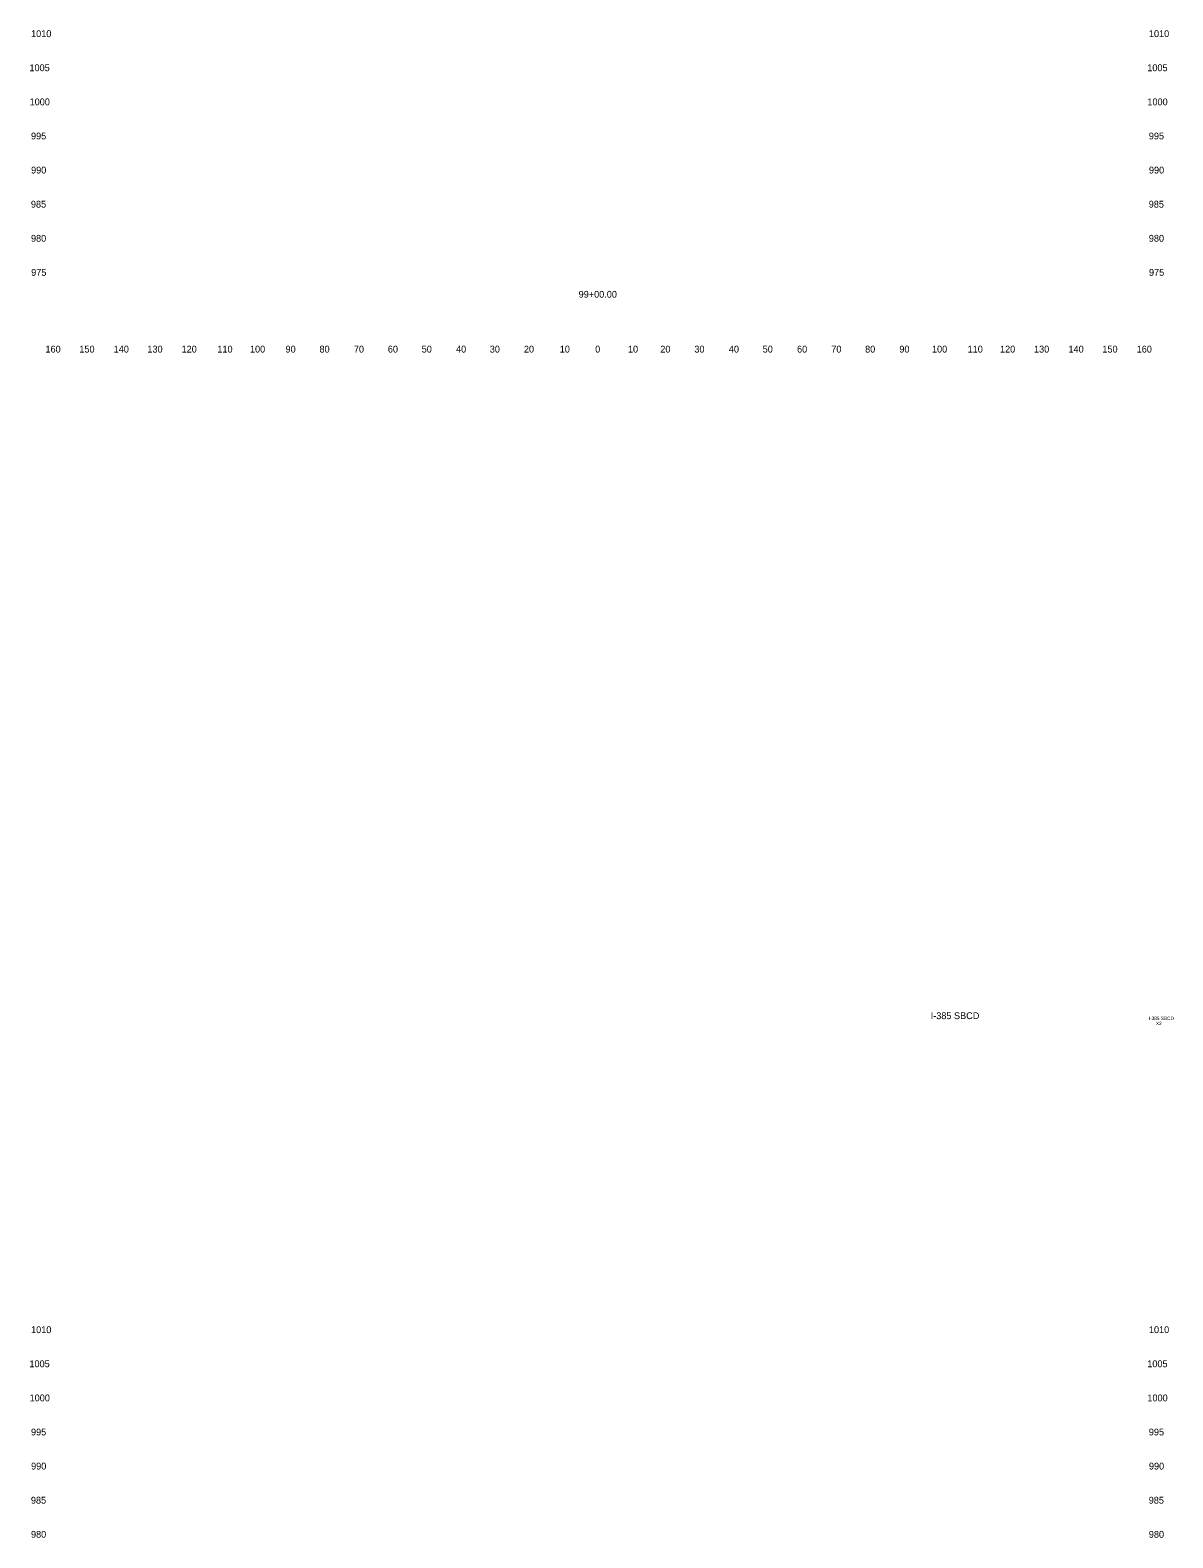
# Model space of a CAD drawing. Extents: x 4994 to 6876, y 4997 to 8804.
# Drawn here: x 4993.6 to 5328.7, y 5450 to 5892 of the extents above; entities that cross this region are included whole.
import ezdxf

# ---------------------------------------------------------------- set-up
doc = ezdxf.new("R2010")
doc.units = 0
for name, color, linetype in [('RD_SHT_ID', 7, 'Continuous'), ('RD_XS_TX_Offset', 7, 'Continuous'), ('RD_XS_TX_Station', 7, 'Continuous')]:
    doc.layers.add(name, color=color, linetype=linetype)

msp = doc.modelspace()

# ---------------------------------------------------------------- texts
at = {"layer": 'RD_SHT_ID'}
for s, height, p in [('I-385 SBCD', 2, (5257.69, 5602.06)), ('I-385 SBCD', 1, (5321.63, 5601.8)), ('X2', 1, (5323.74, 5600.3))]:
    msp.add_text(s, height=height, dxfattribs=at).set_placement(p)
at = {"layer": 'RD_XS_TX_Offset'}
for s, p in [('1010', (4993.88, 5890)), ('1010', (5321.68, 5890)), ('1005', (4993.4, 5880)), ('1005', (5321.2, 5880)), ('1000', (4993.44, 5870)), ('1000', (5321.24, 5870)), ('995', (4993.86, 5860)), ('995', (5321.66, 5860)), ('990', (4993.89, 5850)), ('990', (5321.69, 5850)), ('985', (4993.83, 5840)), ('985', (5321.63, 5840)), ('980', (4993.86, 5830)), ('980', (5321.66, 5830)), ('975', (4993.91, 5820)), ('975', (5321.71, 5820)), ('160', (4998.1, 5797.5)), ('150', (5008.04, 5797.5)), ('140', (5018.1, 5797.5)), ('130', (5027.99, 5797.5)), ('120', (5038.01, 5797.5)), ('110', (5048.51, 5797.5)), ('100', (5058.07, 5797.5)), ('90', (5068.5, 5797.5)), ('80', (5078.46, 5797.5)), ('70', (5088.54, 5797.5)), ('60', (5098.5, 5797.5)), ('50', (5108.43, 5797.5)), ('40', (5118.5, 5797.5)), ('30', (5128.39, 5797.5)), ('20', (5138.4, 5797.5)), ('10', (5148.91, 5797.5)), ('0', (5159.3, 5797.5)), ('0', (5159.3, 5797.5)), ('10', (5168.91, 5797.5)), ('20', (5178.4, 5797.5)), ('30', (5188.39, 5797.5)), ('40', (5198.5, 5797.5)), ('50', (5208.43, 5797.5)), ('60', (5218.5, 5797.5)), ('70', (5228.54, 5797.5)), ('80', (5238.46, 5797.5)), ('90', (5248.5, 5797.5)), ('100', (5258.07, 5797.5)), ('110', (5268.51, 5797.5)), ('120', (5278.01, 5797.5)), ('130', (5287.99, 5797.5)), ('140', (5298.1, 5797.5)), ('150', (5308.04, 5797.5)), ('160', (5318.1, 5797.5)), ('1010', (4993.88, 5510)), ('1010', (5321.68, 5510)), ('1005', (4993.4, 5500)), ('1005', (5321.2, 5500)), ('1000', (4993.44, 5490)), ('1000', (5321.24, 5490)), ('995', (4993.86, 5480)), ('995', (5321.66, 5480)), ('990', (4993.89, 5470)), ('990', (5321.69, 5470)), ('985', (4993.83, 5460)), ('985', (5321.63, 5460)), ('980', (4993.86, 5450)), ('980', (5321.66, 5450))]:
    msp.add_text(s, height=2, dxfattribs=at).set_placement(p)
at = {"layer": 'RD_XS_TX_Station'}
msp.add_text('99+00.00', height=2, dxfattribs=at).set_placement((5154.45, 5813.58))

doc.saveas('drawing.dxf')
